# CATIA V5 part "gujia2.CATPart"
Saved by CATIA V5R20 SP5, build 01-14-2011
Part number: 骨架2
Bounding box of the stored display mesh (mm): x -120 to 0, y -2.5 to 2.5, z 0 to 75
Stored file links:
  E:\180512116\zp\20190505\180512116赵克君\gujia2.CATPart
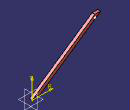
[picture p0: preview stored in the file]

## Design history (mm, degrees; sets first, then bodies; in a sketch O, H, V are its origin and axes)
Body1 (main body)
  Sketch1 on zx-plane, origin (0, 0, 0), H (-1, 0, 0), V (0, 0, 1)
    line L1 (0, 0) -> (3.9678, 0)
    point P2 (120, -75)
    line L2 (0, 0) -> (109.9975, 75)
    line L3 (10.9678, 0) -> (120, 75)
    point P4 (10.9678, 0)
    line L4 (109.9975, 75) -> (120, 75)
    arc A1 centre (7.4678, 0) radius 3.5 from (10.9678, 0) to (3.9678, 0) ccw
    point P5 (7.4678, 0)
    point P6 (10.9678, 0)
    radius A1 = 3.5
    horizontal: L1 H, L4 H
    coincidence: P4 H, P5 L1, A1 P6, P6 L3, P6 H
  Pad1: profile Sketch1, direction (0, 1, 0), length 2.5, mirrored extent
  Sketch2 on end face of Pad1, origin (0, 2.5, 0), H (-1, 0, 0), V (0, 0, 1)
    circle A1 centre (110, 70.1344) radius 1.2589
  Pocket1: profile Sketch2, direction (0, -1, 0), length 10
